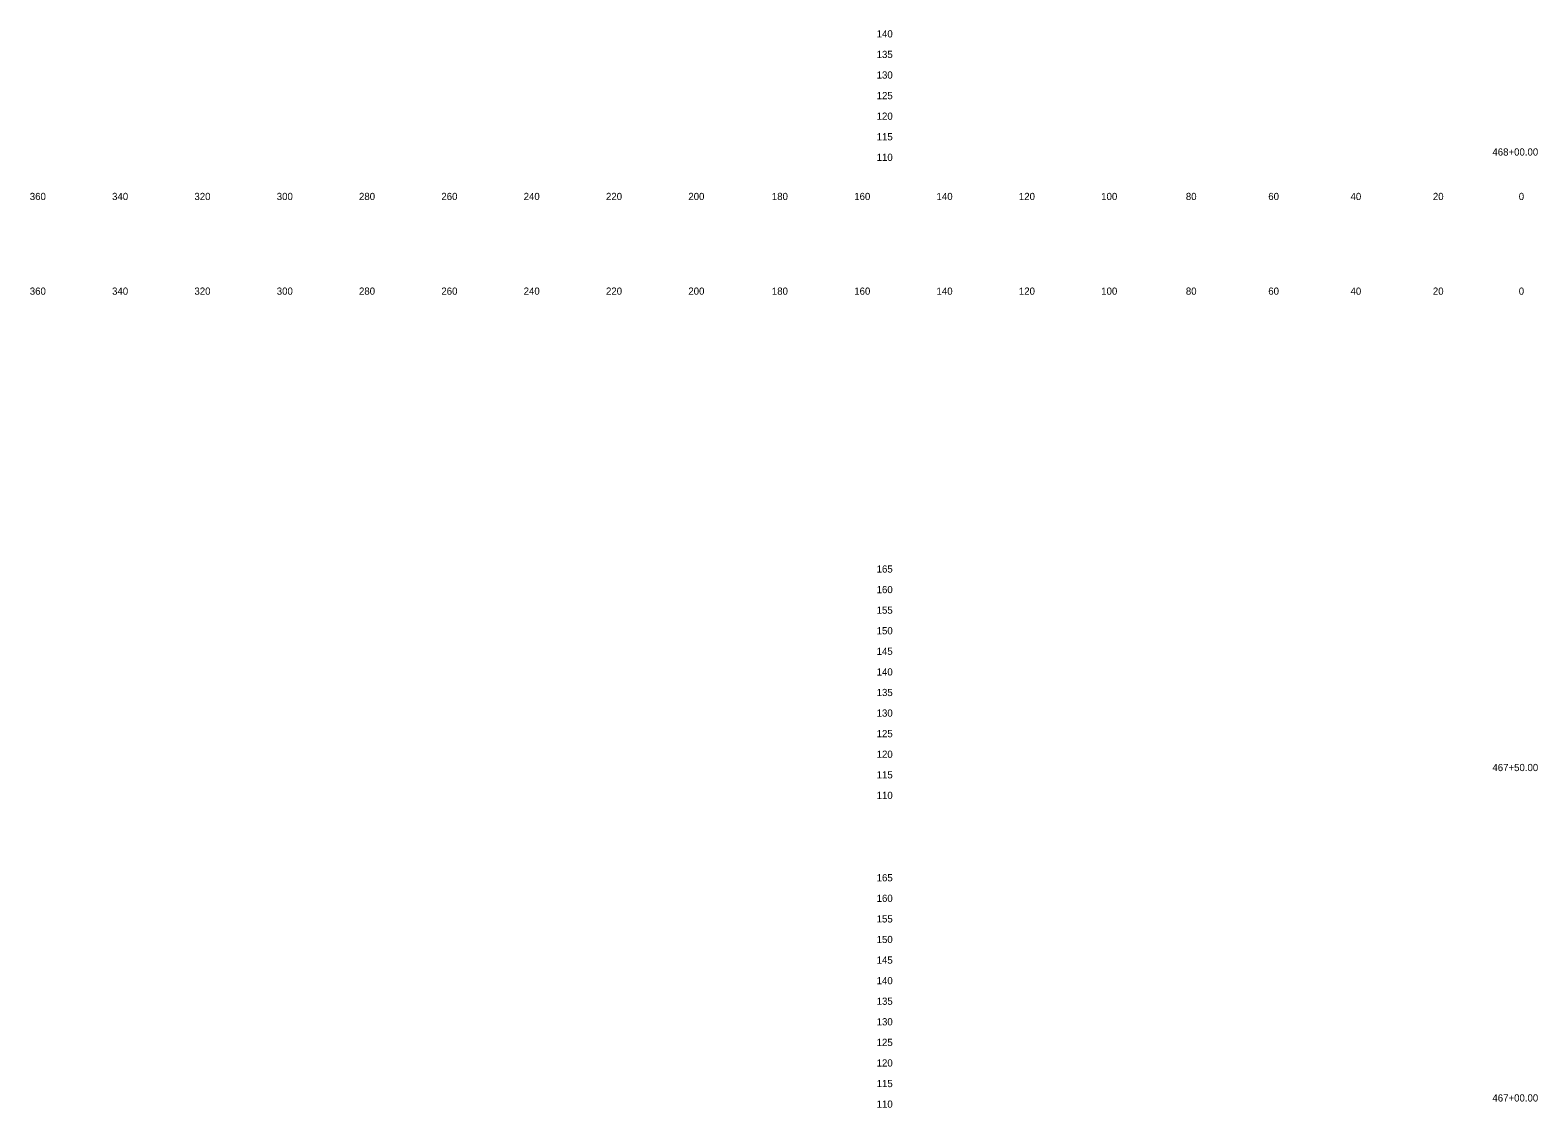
# Model space of a CAD drawing. Extents: x 21281 to 22024, y 6472 to 15198.
# Drawn here: x 21280.5 to 21646.7, y 9474.8 to 9736.6 of the extents above; entities that cross this region are included whole.
import ezdxf

# ---------------------------------------------------------------- set-up
doc = ezdxf.new("R2010")
doc.units = 0
for name, color, linetype in [('Draft_XS_Grid', 7, 'Continuous'), ('Draft_XS_Text', 7, 'Continuous'), ('SLOPE_STAKES_FILL', 7, 'Continuous')]:
    doc.layers.add(name, color=color, linetype=linetype)

msp = doc.modelspace()

# ---------------------------------------------------------------- texts
at = {"layer": 'Draft_XS_Grid'}
for s, p in [('  140  ', (21484.84, 9734.84)), ('  135  ', (21484.84, 9729.84)), ('  130  ', (21484.84, 9724.84)), ('  125  ', (21484.84, 9719.84)), ('  120  ', (21484.84, 9714.84)), ('  115  ', (21484.84, 9709.84)), ('  110  ', (21484.84, 9704.84)), ('  165  ', (21484.84, 9604.84)), ('  160  ', (21484.84, 9599.84)), ('  155  ', (21484.84, 9594.84)), ('  150  ', (21484.84, 9589.84)), ('  145  ', (21484.84, 9584.84)), ('  140  ', (21484.84, 9579.84)), ('  135  ', (21484.84, 9574.84)), ('  130  ', (21484.84, 9569.84)), ('  125  ', (21484.84, 9564.84)), ('  120  ', (21484.84, 9559.84)), ('  115  ', (21484.84, 9554.84)), ('  110  ', (21484.84, 9549.84)), ('  165  ', (21484.84, 9529.84)), ('  160  ', (21484.84, 9524.84)), ('  155  ', (21484.84, 9519.84)), ('  150  ', (21484.84, 9514.84)), ('  145  ', (21484.84, 9509.84)), ('  140  ', (21484.84, 9504.84)), ('  135  ', (21484.84, 9499.84)), ('  130  ', (21484.84, 9494.84)), ('  125  ', (21484.84, 9489.84)), ('  120  ', (21484.84, 9484.84)), ('  115  ', (21484.84, 9479.84)), ('  110  ', (21484.84, 9474.84))]:
    msp.add_text(s, height=1.75, dxfattribs=at).set_placement(p)
at = {"layer": 'Draft_XS_Text'}
for s, p in [('  360  ', (21279.14, 9695.34)), ('  340  ', (21299.13, 9695.34)), ('  320  ', (21319.13, 9695.34)), ('  300  ', (21339.13, 9695.34)), ('  280  ', (21359.1, 9695.34)), ('  260  ', (21379.11, 9695.34)), ('  240  ', (21399.1, 9695.34)), ('  220  ', (21419.1, 9695.34)), ('  200  ', (21439.1, 9695.34)), ('  180  ', (21459.39, 9695.34)), ('  160  ', (21479.4, 9695.34)), ('  140  ', (21499.39, 9695.34)), ('  120  ', (21519.39, 9695.34)), ('  100  ', (21539.39, 9695.34)), ('  80  ', (21559.95, 9695.34)), ('  60  ', (21579.97, 9695.34)), ('  40  ', (21599.95, 9695.34)), ('  20  ', (21619.95, 9695.34)), ('  0  ', (21640.81, 9695.34)), ('  0  ', (21640.81, 9695.34)), ('  360  ', (21279.14, 9672.34)), ('  340  ', (21299.13, 9672.34)), ('  320  ', (21319.13, 9672.34)), ('  300  ', (21339.13, 9672.34)), ('  280  ', (21359.1, 9672.34)), ('  260  ', (21379.11, 9672.34)), ('  240  ', (21399.1, 9672.34)), ('  220  ', (21419.1, 9672.34)), ('  200  ', (21439.1, 9672.34)), ('  180  ', (21459.39, 9672.34)), ('  160  ', (21479.4, 9672.34)), ('  140  ', (21499.39, 9672.34)), ('  120  ', (21519.39, 9672.34)), ('  100  ', (21539.39, 9672.34)), ('  80  ', (21559.95, 9672.34)), ('  60  ', (21579.97, 9672.34)), ('  40  ', (21599.95, 9672.34)), ('  20  ', (21619.95, 9672.34)), ('  0  ', (21640.81, 9672.34)), ('  0  ', (21640.81, 9672.34))]:
    msp.add_text(s, height=1.75, dxfattribs=at).set_placement(p)
at = {"layer": 'SLOPE_STAKES_FILL'}
for s, p in [('  468+00.00  ', (21634.41, 9706.14)), ('  467+50.00  ', (21634.41, 9556.61)), ('  467+00.00  ', (21634.41, 9476.34))]:
    msp.add_text(s, height=1.75, dxfattribs=at).set_placement(p)

doc.saveas('drawing.dxf')
